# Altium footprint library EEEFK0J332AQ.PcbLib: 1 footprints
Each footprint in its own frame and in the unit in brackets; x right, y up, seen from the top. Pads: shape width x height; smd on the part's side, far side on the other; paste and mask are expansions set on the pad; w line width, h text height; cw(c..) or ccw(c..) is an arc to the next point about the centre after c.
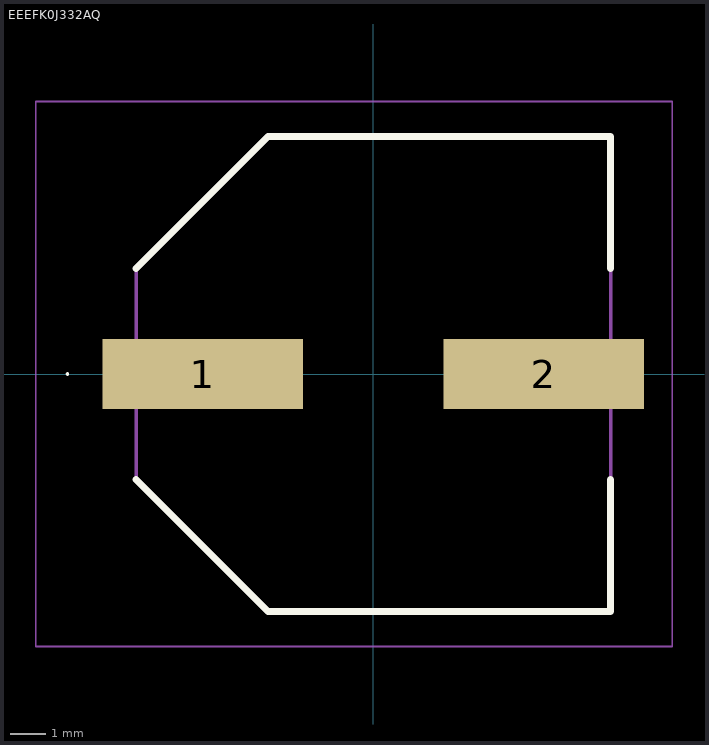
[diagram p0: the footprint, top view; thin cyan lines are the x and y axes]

## EEEFK0J332AQ [mm]
pads (2):
  rect 5.7x2 smd: 1(-4.85,0) 2(4.85,0)
Top Overlay:
  lines w0.05: -8.725,0 -8.725,0 ; -8.725,0 ccw(c-8.7,0) -8.675,0 ; -8.725,0 cw(c-8.7,0) -8.675,0 ; -8.675,0 -8.675,0
  lines w0.2: -6.75,-3 -3,-6.75 6.75,-6.75 6.75,-3 ; -6.75,3 -3,6.75 6.75,6.75 6.75,3
Mechanical 15:
  lines w0.1: -6.75,3 -3,6.75 ; -6.75,3 -6.75,-3 -3,-6.75 6.75,-6.75 6.75,6.75 -3,6.75 ; -6.75,3 -3,6.75
Mechanical 20:
  lines w0.05: -9.6,-7.75 8.5,-7.75 8.5,7.75 -9.6,7.75 -9.6,-7.75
